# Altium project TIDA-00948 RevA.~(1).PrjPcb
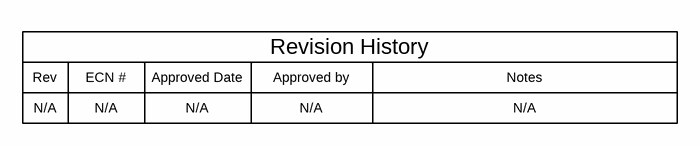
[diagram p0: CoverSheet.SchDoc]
CopyrightYear: 2015; EVM_Orderable: N/A; PCB_Layout: Who did the Layout?; PCB_Rev: E1; PRJ_Customer: Public Release; PRJ_Engineer: Enter name of project lead; PRJ_Number: TIDA-xxxxx; PRJ_Title: Change in menu Project|Project Options|Parameters; SCH_Rev: E1; TechSupport: http://www.ti.com/support; TID: ChangeMe!
2 sheets, 19 parts. Net scope: global (net labels, ports and power ports of the same name join across sheets).
Board file: TID.PcbDoc
Sheets:
  CoverSheet.SchDoc
  TID_Hardware.SchDoc

## Sheet CoverSheet.SchDoc
size 431 x 279 mm; Date: Not shown in title block; ApprovedBy: Not shown in title block; CheckedBy: Not shown in title block; Author: Not shown in title block; CompanyName: Not shown in title block; Engineer: Not shown in title block; Organization: Not shown in title block; Address1: Not shown in title block; Address2: Not shown in title block; Address3: Not shown in title block; Address4: Not shown in title block; DocumentNumber: 1; Revision: Use project parameter SCH_Rev; SheetNumber: 1; SheetTotal: 3; PageSetup: Record=PageOptions¦CenterHorizontal=True¦CenterVertical=True¦PrintScale=1.00¦XCorrection=1.00¦YCorrection=1.00¦PrintKind=0¦BorderSize=5000000¦LeftOffset=0¦BottomOffset=0¦Orientation=2¦PaperLength=1000¦PaperWidth=1000¦Scale=100¦PaperSource=15¦PrintQuality=600¦MediaType=1¦DitherType=10¦PaperKind=Letter¦PrintScaleMode=1

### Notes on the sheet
- Rev
- N/A
- ECN #
- Approved Date
- Approved by
- Revision History
- Notes

## Sheet TID_Hardware.SchDoc
size 431 x 279 mm; Date: Not shown in title block; ApprovedBy: Not shown in title block; CheckedBy: Not shown in title block; Author: Not shown in title block; CompanyName: Not shown in title block; Engineer: Not shown in title block; Organization: Not shown in title block; Address1: Not shown in title block; Address2: Not shown in title block; Address3: Not shown in title block; Address4: Not shown in title block; DocumentNumber: 1; Revision: Use project parameter SCH_Rev; SheetNumber: 3; SheetTotal: 3; PageSetup: Record=PageOptions¦CenterHorizontal=True¦CenterVertical=True¦PrintScale=1.00¦XCorrection=1.00¦YCorrection=1.00¦PrintKind=0¦BorderSize=5000000¦LeftOffset=0¦BottomOffset=0¦Orientation=2¦PaperLength=1000¦PaperWidth=1000¦Scale=100¦PaperSource=15¦PrintQuality=600¦MediaType=1¦DitherType=10¦PaperKind=Letter¦PrintScaleMode=1
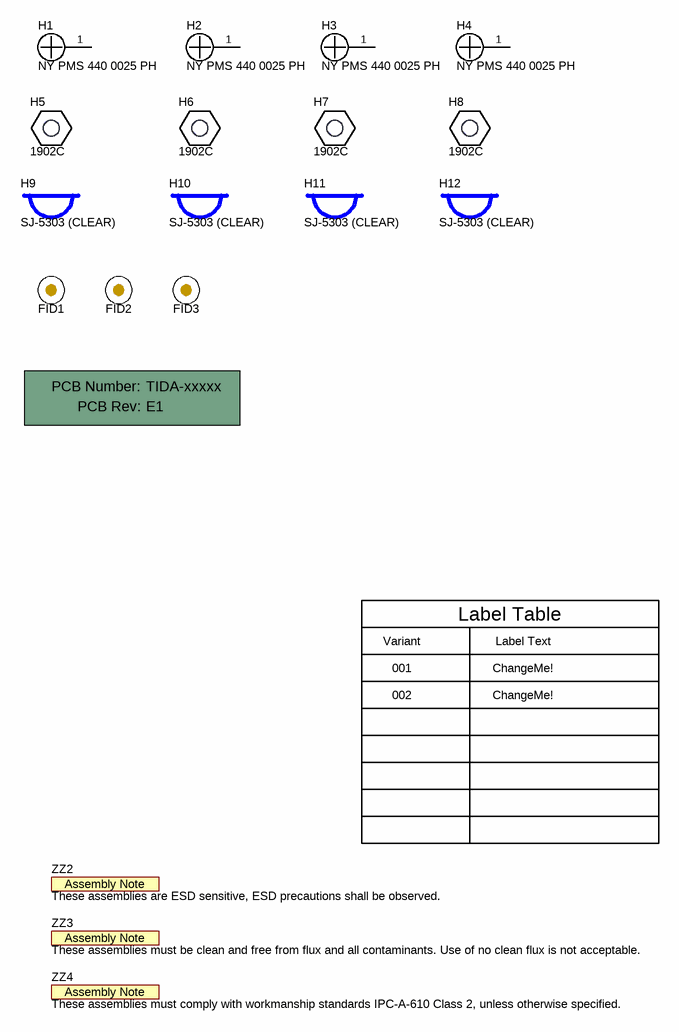
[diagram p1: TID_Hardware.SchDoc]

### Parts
!PCB  Printed Circuit Board  (value not drawn)  (mechanical)
FID1  Fiducial  [Fiducial10-20]  (value not drawn)
FID2  Fiducial  [Fiducial10-20]  (value not drawn)
FID3  Fiducial  [Fiducial10-20]  (value not drawn)
H1  NY PMS 440 0025 PH  [NY PMS 440 0025 PH]
H2  NY PMS 440 0025 PH  [NY PMS 440 0025 PH]
H3  NY PMS 440 0025 PH  [NY PMS 440 0025 PH]
H4  NY PMS 440 0025 PH  [NY PMS 440 0025 PH]
H5  1902C  [Keystone_1902C]
H6  1902C  [Keystone_1902C]
H7  1902C  [Keystone_1902C]
H8  1902C  [Keystone_1902C]
H9  SJ-5303 (CLEAR)  [Bumpon_SJ5003Transparent]
H10  SJ-5303 (CLEAR)  [Bumpon_SJ5003Transparent]
H11  SJ-5303 (CLEAR)  [Bumpon_SJ5003Transparent]
H12  SJ-5303 (CLEAR)  [Bumpon_SJ5003Transparent]
ZZ2  These assemblies are ESD sensitive, ESD precautions shall be observed.  [AssemblyNote]  (no BOM)
ZZ3  These assemblies must be clean and free from flux and all contaminants. Use of no clean flux is not acceptable.  [AssemblyNote]  (no BOM)
ZZ4  These assemblies must comply with workmanship standards IPC-A-610 Class 2, unless otherwise specified.  [AssemblyNote]  (no BOM)

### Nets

Not connected (* = marked no-connect by the designer): H1 1; H2 1; H3 1; H4 1

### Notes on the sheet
- Variant
- Label Table
- Label Text
- 001
- 002
- ChangeMe!

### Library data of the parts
!PCB = PCB: Manufacturer: Any; PartNumber: TIDA-xxxxx; SymbolCreator: a0412235
FID1-FID3 = Fiducial: Fiducial mark.  There is nothing to buy or mount.; SymbolCreator: codlsc
H1-H4 = NY PMS 440 0025 PH: Machine Screw, Round, #4-40 x 1/4, Nylon, Philips panhead; Manufacturer: B&F Fastener Supply; CompType: Hardware; SymbolCreator: codlsc; U/M: EA
H5-H8 = 1902C: Standoff, Hex, 0.5"L #4-40 Nylon; Manufacturer: Keystone; CompType: Hardware
H9-H12 = SJ-5303 (CLEAR): Bumpon, Hemisphere, 0.44 X 0.20, Clear; Manufacturer: 3M; SymbolCreator: a0412235
ZZ2-ZZ4 = AssemblyNote: SymbolCreator: codlsc

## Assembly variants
001: not fitted FID1 FID2 FID3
